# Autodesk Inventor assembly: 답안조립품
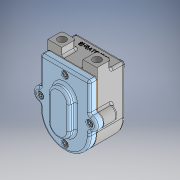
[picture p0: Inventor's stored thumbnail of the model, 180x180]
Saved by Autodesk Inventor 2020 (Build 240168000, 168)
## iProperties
Created: 2024-03
Part Number: 답안조립품
Document SubType Name: Assembly
Designer: 1강의실14
Author: 1강의실14
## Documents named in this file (9)
- C:\Users\1강의실14\Desktop\740304V1015\답안조립품.iam
- C:\Users\1강의실14\Desktop\740304V1015\본체.ipt
- C:\Users\1강의실14\Desktop\740304V1015\오일레스 부시.ipt
- C:\Users\1강의실14\Desktop\740304V1015\구동기어.ipt
- C:\Users\1강의실14\Desktop\740304V1015\오일 실 14 25 7.ipt
- C:\Users\1강의실14\Desktop\740304V1015\스퍼기어.ipt
- C:\Users\1강의실14\Desktop\740304V1015\가스켓.ipt
- C:\Users\1강의실14\Desktop\740304V1015\커버.ipt
- C:\Users\1강의실14\Desktop\740304V1015\육각 소켓 머리 볼트 M5x12.ipt
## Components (2 placed, 2 different names)
1. 구동기어:1
2. 가스켓:1
